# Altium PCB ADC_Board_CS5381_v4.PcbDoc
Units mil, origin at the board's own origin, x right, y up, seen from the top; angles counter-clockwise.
Board outline 7645 x 5670 mil, 2 copper layers (Top Layer, Bottom Layer); 112 components, 61 nets, 314 pads, 13 vias.
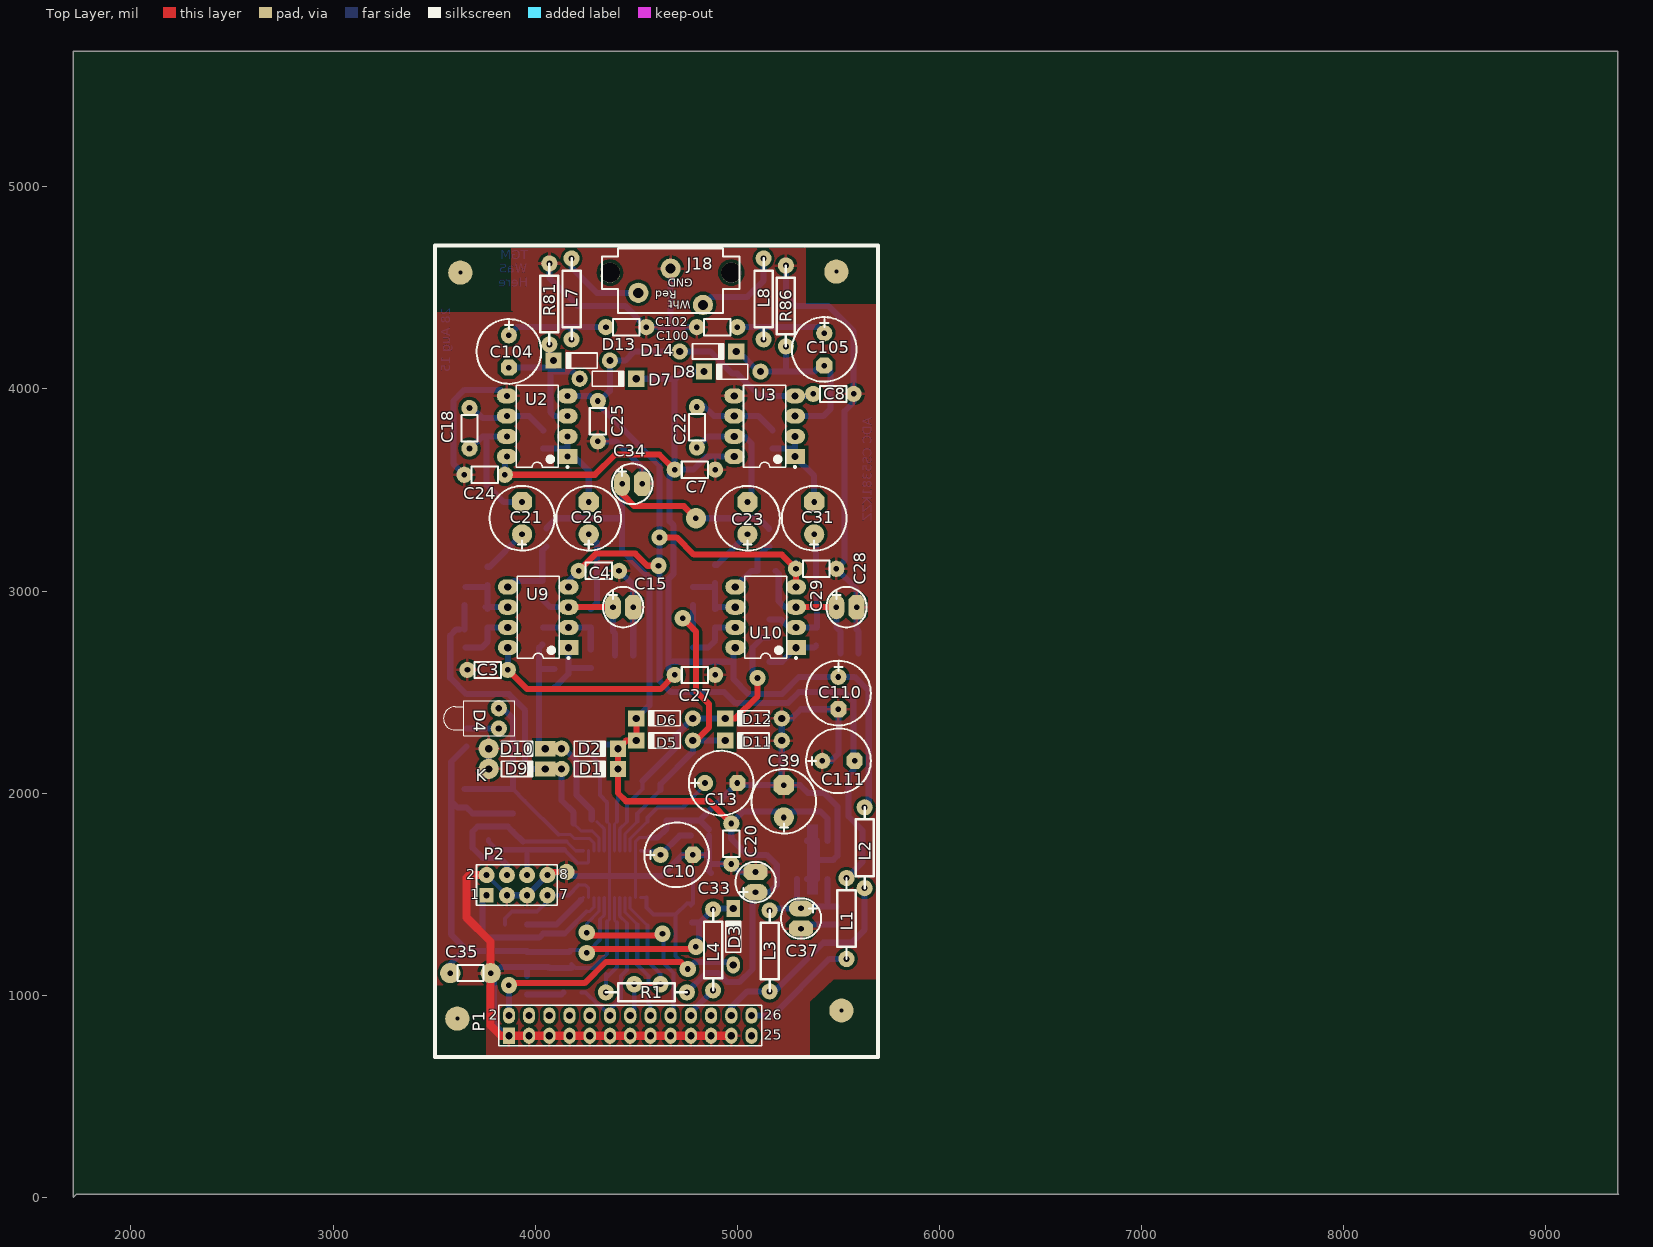
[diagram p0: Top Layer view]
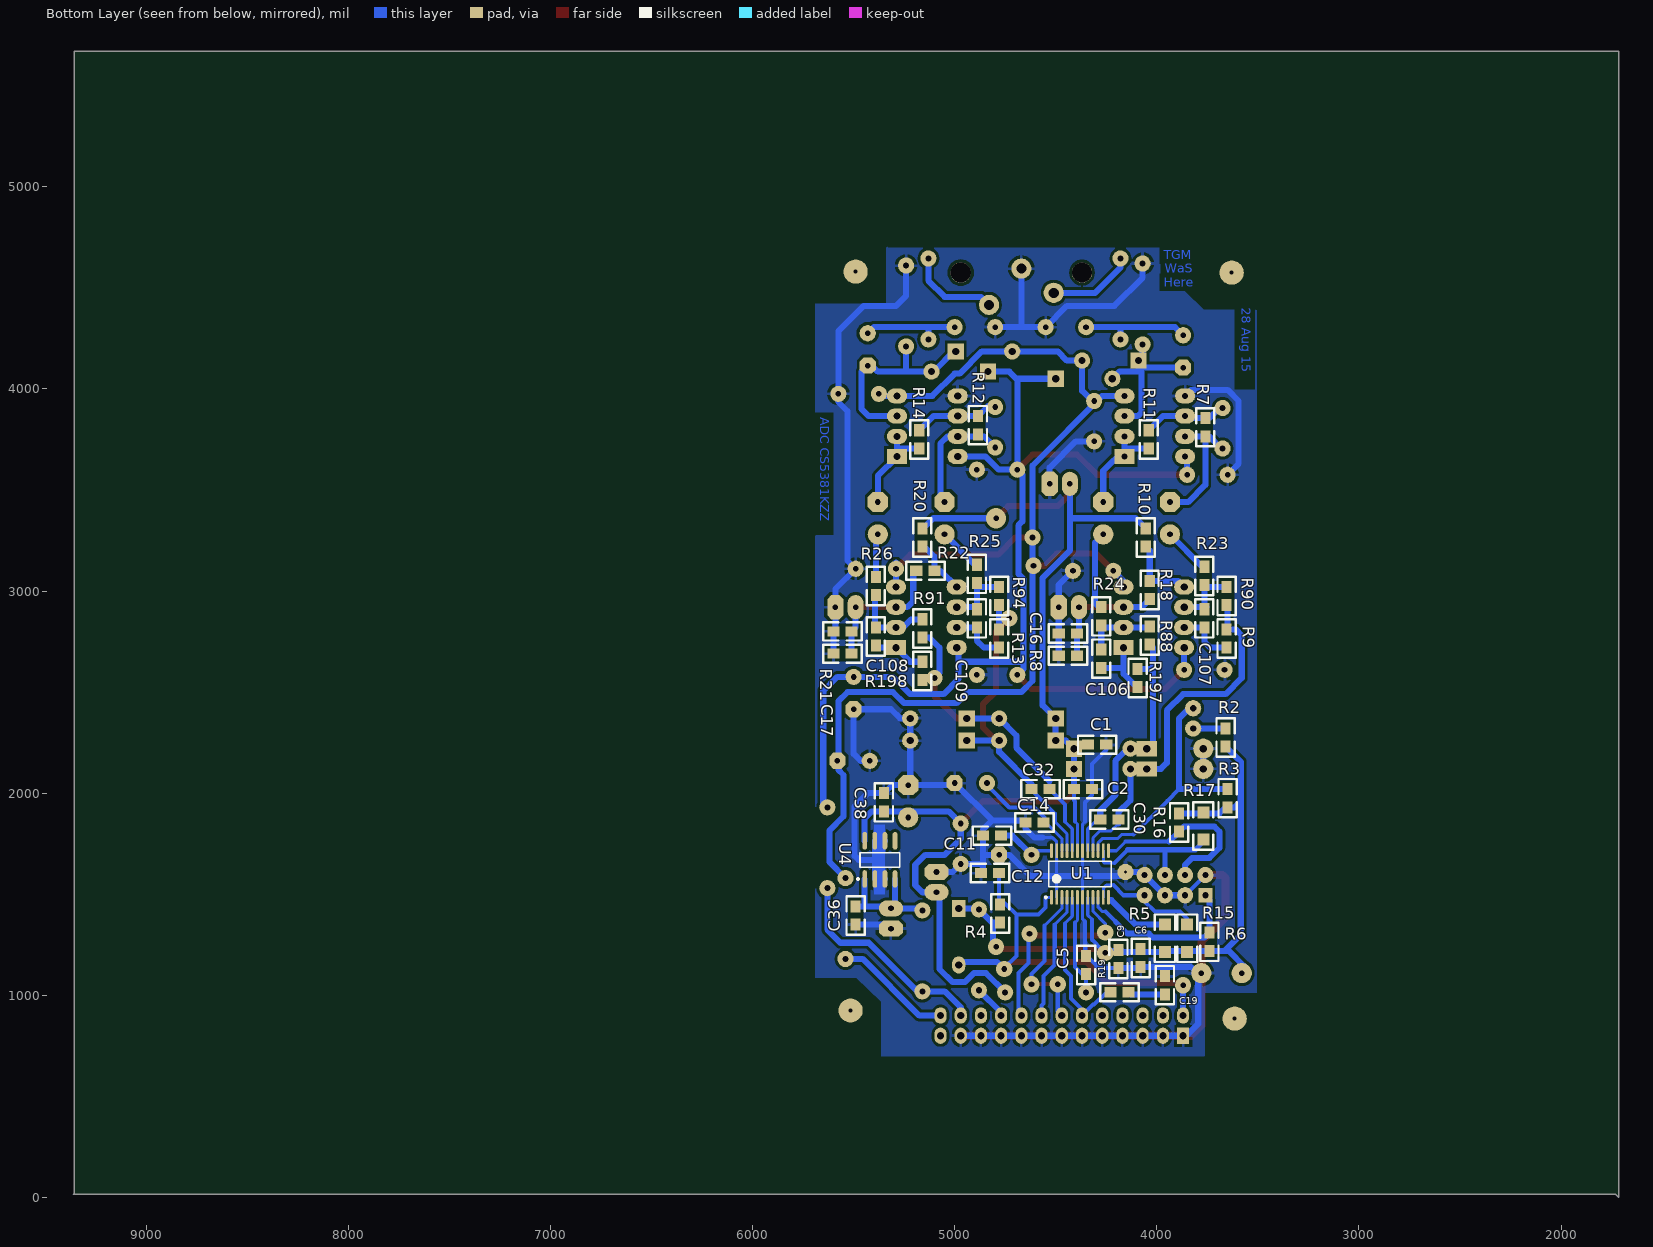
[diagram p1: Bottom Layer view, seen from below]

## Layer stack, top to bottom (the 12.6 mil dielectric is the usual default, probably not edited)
Top Layer: signal copper 1.4
Dielectric: core 12.6, FR-4, Dk 4.8
Bottom Layer: signal copper 1.4

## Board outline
1715,5670 9355,5670 9355,20 9360,15 1730,15 1715,0

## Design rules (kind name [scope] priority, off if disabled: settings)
Clearance Clearance_1 [(IsRegion)] p1: gap=15
Clearance [All] p2: gap=10
ComponentClearance [All] p1: gap=5 collisioncheckmode=3 verticalgap=10 showdistances=FALSE
HoleSize [All] p1: absolutevalues=TRUE maxlimit=125 minlimit=1 maxpercent=80.000 minpercent=20.000
PermittedLayers [All] p1: toplayerpermitted=TRUE bottomlayerpermitted=TRUE
PolygonConnect [All] p1: connectstyle=Relief reliefconductorwidth=15 reliefentries=4 polygonreliefangle="90 Angle"
RoutingVias [All] p1: holewidth=28 width=50 viastyle="Through Hole" minholewidth=28 minwidth=50 maxholewidth=28 maxwidth=50
SilkscreenOverComponentPads [All] p1: minsilkscreentomaskgap=10
SolderMaskExpansion [All] p1: expansion=4
Width [All] p1: maxlimit=255 minlimit=10 preferedwidth=10 minimp=50.000000 maximp=50.000000 favimp=50.000000
25 further rules are at their usual default settings.

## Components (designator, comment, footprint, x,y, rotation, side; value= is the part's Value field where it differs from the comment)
C1 "1uF" 0805 4340,2240 r180 bottom
C2 "10n" 0805 4410,2020 r180 bottom
C3 "100n" AXIAL0.2-pth#1 3865,2610 r180 top
C4 "100n" AXIAL0.2-pth#1 4415,3100 r180 top
C5 "10n" 0805 4350,1105 r90 bottom
C6 "1uF" 0805 4080,1230 r270 bottom
C7 "100n" AXIAL0.2-pth#1 4690,3600 r0 top
C8 "100n" AXIAL0.2-pth#1 5575,3975 r180 top
C9 "10n" 0805 4190,1225 r270 bottom
C10 "220uF" RB.16/.32-pth#1 4780,1695 r180 top
C11 "10n" 0805 4770,1790 r0 bottom
C12 "100n" 0805 4870,1605 r180 bottom
C13 "1uF" RB.16/.32-pth#1 5000,2050 r180 top
C14 "10n" 0805 4650,1855 r180 bottom
C15 "10uF" RB.1/.2 4485,2920 r180 top
C16 "100n" 0805 4395,2790 r0 bottom
C17 "100n" 0805 5510,2690 r0 bottom
C18 "33pF" AXIAL0.2-pth#1 3675,3905 r270 top
C19 "27pF" 0805 3960,1005 r90 bottom
C20 "100n" AXIAL0.2-pth#1 4970,1850 r270 top
C21 "47uF" RB.16/.32-pth#2 3935,3440 r270 top
C22 "33pF" AXIAL0.2-pth#1 4800,3910 r270 top
C23 "47uF" RB.16/.32-pth#2 5050,3440 r270 top
C24 "100n" AXIAL0.2-pth#1 3850,3575 r180 top
C25 "100n" AXIAL0.2-pth#1 4310,3740 r90 top
C26 "47uF" RB.16/.32-pth#2 4265,3440 r270 top
C27 "100n" AXIAL0.2-pth#1 4690,2585 r0 top
C28 "10uF" RB.1/.2 5590,2920 r180 top
C29 "100n" AXIAL0.2-pth#1 5490,3110 r180 top
C30 "2700pF" 0805 4280,1870 r180 bottom
C31 "47uF" RB.16/.32-pth#2 5380,3440 r270 top
C32 "2700pF" 0805 4530,2020 r0 bottom
C33 "10uF" RB.1/.2 5090,1610 r270 top
C34 "10uF" RB.1/.2 4530,3530 r180 top
C35 "100n" AXIAL0.2-pth#2 3580,1110 r0 top
C36 "100n" 0805 5490,1440 r270 bottom
C37 "220uF" RB.1/.2 5315,1330 r90 top
C38 "100n" 0805 5350,1910 r90 bottom
C39 "220uF" RB.16/.32-pth#2 5230,2040 r270 top
C100 "100pF" AXIAL0.2-pth#1 4350,4305 r0 top
C102 "100pF" AXIAL0.2-pth#1 4800,4305 r0 top
C104 "47uF" RB.16/.32-PTH 3870,4105 r90 top
C105 "47uF" RB.16/.32-PTH 5430,4115 r90 top
C106 "1nF" 0805 4275,2620 r90 bottom
C107 "1nF" 0805 3765,2910 r270 bottom
C108 "1nF" 0805 5390,2730 r90 bottom
C109 "1nF" 0805 4890,2910 r270 bottom
C110 "22uF" RB.16/.32-pth#1 5500,2415 r90 top
C111 "22uF" RB.16/.32-pth#1 5580,2160 r180 top
D1 "BAT85" DIO7.1-3.9x1.9#1 4270,2120 r0 top
D2 "BAT85" DIO7.1-3.9x1.9#1 4270,2220 r0 top
D3 "Diode 1N914" DIO7.1-3.9x1.9#2 4980,1290 r90 top
D4 "LED0" LED-1 3820,2370 r180 top
D5 "BAT85" DIO7.1-3.9x1.9#1 4640,2260 r180 top
D6 "BAT85" DIO7.1-3.9x1.9#1 4640,2370 r180 top
D7 "BAT85" DIO7.1-3.9x1.9#1 4360,4050 r0 top
D8 "BAT85" DIO7.1-3.9x1.9#1 4975,4085 r180 top
D9 "BAT85" DIO7.1-3.9x1.9#3 3910,2120 r0 top
D10 "BAT85" DIO7.1-3.9x1.9#3 3910,2220 r0 top
D11 "BAT85" DIO7.1-3.9x1.9#1 5080,2260 r180 top
D12 "BAT85" DIO7.1-3.9x1.9#1 5080,2370 r180 top
D13 "BAT85" DIO7.1-3.9x1.9#1 4230,4140 r180 top
D14 "BAT85" DIO7.1-3.9x1.9#1 4855,4185 r0 top
J18 "Analog Input" RCA-PCB-2IP 4510,4475 r180 top
L1 "bead" AXIAL0.4-PTH 5540,1580 r270 top
L2 "bead" AXIAL0.4-PTH 5630,1930 r270 top
L3 "bead" AXIAL0.4-PTH 5160,1020 r90 top
L4 "bead" AXIAL0.4-PTH 4880,1425 r270 top
L7 "bead" AXIAL0.4-PTH 4180,4645 r270 top
L8 "bead" AXIAL0.4-PTH 5130,4245 r90 top
P1 "Header 13X2" HDR2X13 3870,800 r0 top
P2 "Header 4X2" HDR2X4 3760,1495 r0 top
R1 "5R1" AXIAL0.4-PTH 4750,1015 r180 top
R2 "1K" 0805 3660,2320 r270 bottom
R3 "10K" 0805 3650,2020 r270 bottom
R4 "10K" 0805 4774.8,1449.8 r270 bottom
R5 "10K" 1206 3960,1350 r270 bottom
R6 "10K" 0805 3740,1310 r270 bottom
R7 "4k7" 0805 3760,3855 r270 bottom
R8 "10K" 0805 4395,2680 r0 bottom
R9 "91" 0805 3655,2720 r90 bottom
R10 "10K" 0805 4055,3310 r270 bottom
R11 "4k7" 0805 4040,3705 r90 bottom
R12 "4k7" 0805 4885,3865 r270 bottom
R13 "91" 0805 4780,2720 r90 bottom
R14 "4k7" 0805 5175,3705 r90 bottom
R15 "10K" 1206 3850,1350 r270 bottom
R16 "10K" 0805 3890,1810 r90 bottom
R17 "10K" 1206 3770,1770 r90 bottom
R18 "8r2" 0805 4035,3050 r270 bottom
R19 "100R" 0805 4230,1015 r180 bottom
R20 "10K" 0805 5160,3310 r270 bottom
R21 "10K" 0805 5510,2800 r0 bottom
R22 "8r2" 0805 5100,3100 r0 bottom
R23 "680" 0805 3765,3120 r270 bottom
R24 "680" 0805 4275,2920 r270 bottom
R25 "680" 0805 4890,3130 r270 bottom
R26 "680" 0805 5390,3070 r270 bottom
R81 "100K" AXIAL0.4-PTH 4070,4620 r270 top
R86 "100K" AXIAL0.4-PTH 5240,4610 r270 top
R88 "680" 0805 4035,2825 r270 bottom
R90 "680" 0805 3655,3020 r270 bottom
R91 "680" 0805 5160,2860 r270 bottom
R94 "680" 0805 4780,3020 r270 bottom
R197 "91" 0805 4095,2525 r90 bottom
R198 "91" 0805 5160,2650 r270 bottom
U1 "CS5361" TSOP65P640X120-24M 4380,1600 r90 bottom
U2 "NE5532" DIP-8#1 4010,3815 r180 top
U3 "NE5532" DIP-8#2 5135,3815 r180 top
U4 "MC33375D-5.0R2" 751-05_N 5370,1670 r90 bottom
U9 "NE5532" DIP-8#3 4015,2870 r180 top
U10 "NE5532" DIP-8#3 5140,2870 r180 top

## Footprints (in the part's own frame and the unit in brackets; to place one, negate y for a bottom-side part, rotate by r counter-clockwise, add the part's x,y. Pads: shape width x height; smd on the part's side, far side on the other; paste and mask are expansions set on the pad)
751-05_N [mm] "SOIC, 8-Leads, Body 4.9x3.9mm, Pitch 1.27mm, IPC Medium Density"
  oval 2.2x0.6 smd: 1(-2.4,1.905) 2(-2.4,0.635) 3(-2.4,-0.635) 4(-2.4,-1.905) 5(2.4,-1.905) 6(2.4,-0.635) 7(2.4,0.635) 8(2.4,1.905)
  silkscreen extent -2.52,-2.5 0.9,2.88, body extent -1.95,-2.45 1.95,2.45, height 1.75
0805 [mil]
  rect 60x50 smd: 1(0,0) 2(90,0)
  silkscreen extent -50,-45 140,45
1206 [mil]
  rect 60x60 smd: 1(0,0) 2(135,0)
  silkscreen extent -50,-50 185,50, body extent -56,-56 191,56, height 8
AXIAL0.2-pth#1 [mil]
  round 80 hole 28: 1(0,0) 2(200,0)
  silkscreen extent 35,-40 165,40
AXIAL0.2-pth#2 [mil]
  round 100 hole 28: 1(0,0) 2(200,0)
  silkscreen extent 35,-40 165,40, body extent 30,-45 170,45, height 200
AXIAL0.4-PTH [mil]
  round 80 hole 30: 1(0,0) 2(400,0)
  silkscreen extent 0,-45 400,45, body extent 60,-45 340,45
DIO7.1-3.9x1.9#1 [mil] "Diode, Axial; Body 3.8 x 1.9 mm (LxDia. max), Lead Dia. 0.53 mm (max)"
  round 80 hole 35.43: 1(-139.76,0)
  rect 80x80 hole 35.43: 2(139.76,0)
  silkscreen extent -77,-37 81,37
DIO7.1-3.9x1.9#2 [mil] "Diode, Axial; Body 3.8 x 1.9 mm (LxDia. max), Lead Dia. 0.53 mm (max)"
  oval 85x65 hole 35.43: 1(-139.76,0)
  rect 85x65 hole 35.43: 2(139.76,0)
  silkscreen extent -77,-37 81,37
DIO7.1-3.9x1.9#3 [mil] "Diode, Axial; Body 3.8 x 1.9 mm (LxDia. max), Lead Dia. 0.53 mm (max)"
  round 100 hole 35.43: 1(-139.76,0)
  rect 100x75 hole 35.43: 2(139.76,0)
  silkscreen extent -77,-37 81,37
DIP-8#1 [mil] "DIP; 8 Leads; Row Spacing 7.62 mm; Pitch 2.54 mm"
  rect 100x75 hole 30: 1(-150,150)
  oval 100x75 hole 30: 2(-150,50) 3(-150,-50) 4(-150,-150) 5(150,-150) 6(150,-50) 7(150,50) 8(150,150)
  silkscreen extent -155,-203 104,206, body extent -142,-203 142,203, height 200
DIP-8#2 [mil] "DIP; 8 Leads; Row Spacing 7.62 mm; Pitch 2.54 mm"
  rect 100x75 hole 35.43: 1(-150,150)
  oval 100x75 hole 35.43: 2(-150,50) 3(-150,-50) 4(-150,-150) 5(150,-150) 6(150,-50) 7(150,50) 8(150,150)
  silkscreen extent -155,-203 104,206, body extent -142,-203 142,203, height 200
DIP-8#3 [mil] "DIP, 8-Pin, Row Spacing 7.62 mm, Pitch 2.54 mm"
  rect 100x75 hole 36: 1(-150,150)
  oval 100x75 hole 36: 2(-150,50) 3(-150,-50) 4(-150,-150) 5(150,-150) 6(150,-50) 7(150,50) 8(150,150)
  silkscreen extent -155,-203 104,206, body extent -142,-203 142,203, height 210
HDR2X4 [mil] "Connector; Header; 4x2 Position"
  rect 70x70 hole 30: 1(0,0)
  round 80 hole 30: 2(0,100) 3(100,0) 4(100,100) 5(200,0) 6(200,100) 7(300,0) 8(300,100)
  silkscreen extent -50,-50 350,150
HDR2X13 [mil] "Connector; Header; 13x2 Position"
  rect 60x80 hole 35.43: 1(0,0)
  oval 60x80 hole 35.43: 2(0,100) 3(100,0) 4(100,100) 5(200,0) 6(200,100) 7(300,0) 8(300,100) 9(400,0) 10(400,100) 11(500,0) 12(500,100) 13(600,0) 14(600,100) 15(700,0) 16(700,100) 17(800,0) 18(800,100) 19(900,0) 20(900,100) 21(1000,0) 22(1000,100) 23(1100,0) 24(1100,100) 25(1200,0) 26(1200,100)
  silkscreen extent -50,-50 1250,150
LED-1 [mil] "Typical RED GaAs LED; 2 Leads"
  round 80 hole 31.5: 1(0,50) 2(0,-50)
  silkscreen extent -79,-87 274,87
RB.1/.2 [mil]
  oval 80x120 hole 28: 1(100,0)
  oct 80x120 hole 28: 2(0,0)
  silkscreen extent -50,-100 150,100, body extent -50,-100 150,100
RB.16/.32-pth#1 [mil]
  round 80 hole 28: 1(160,0)
  oct 80x80 hole 28: 2(0,0)
  silkscreen extent -80,-160 240,160
RB.16/.32-pth#2 [mil]
  round 100 hole 28: 1(160,0)
  oct 100x100 hole 28: 2(0,0)
  silkscreen extent -80,-160 240,160, body extent -80,-160 240,160, height 540
RB.16/.32-PTH [mil]
  round 80 hole 28: 1(160,0)
  oct 80x80 hole 28: 2(0,0)
  silkscreen extent -80,-160 240,160, body extent -80,-160 240,160, height 540
RCA-PCB-2IP [mil]
  round 100 hole 100: 0(-460,-100) 0(140,-100)
  round 100 hole 50: 1(0,0) 2(-160,-120) 3(-320,60)
  silkscreen extent -500,-220 180,100
TSOP65P640X120-24M [mm] "TSOP, 24-Leads, Body 7.9x4.5mm (max), Pitch 0.65mm, IPC Low Density"
  oval 1.85x0.35 smd: 1(-2.925,3.575) 2(-2.925,2.925) 3(-2.925,2.275) 4(-2.925,1.625) 5(-2.925,0.975) 6(-2.925,0.325) 7(-2.925,-0.325) 8(-2.925,-0.975) 9(-2.925,-1.625) 10(-2.925,-2.275) 11(-2.925,-2.925) 12(-2.925,-3.575) 13(2.925,-3.575) 14(2.925,-2.925) 15(2.925,-2.275) 16(2.925,-1.625) 17(2.925,-0.975) 18(2.925,-0.325) 19(2.925,0.325) 20(2.925,0.975) 21(2.925,1.625) 22(2.925,2.275) 23(2.925,2.925) 24(2.925,3.575)
  silkscreen extent -3.05,-3.95 1.6,4.43, body extent -2.25,-3.95 2.25,3.95, height 1.2

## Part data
C1 C3 C4 C5 C6 C7 C8 C9 C11 C14 C16 C17 C18 C20 C22 C24 C25 C27 C29 C30 C32 C35 C36 C38 C100 C102 C104 C105 C106 C107 C108 C109: library part CAP
C2: library part Cap
C10 C13 C15 C21 C23 C26 C28 C31 C33 C34 C37 C39 C110 C111: library part CAPACITOR, "Capacitor"
C12: library part Cap, "Capacitor"
C19: library part CAP, "Capacitor"
D1 D2 D5 D6 D7 D8 D9 D10 D11 D12 D13 D14: library part "Diode 1N914", "Shottky Diode"
D3: "High Conductance Fast Diode"
D4: "Typical INFRARED GaAs LED"
J18: library part RCA-PCB-2IP
L1 L2 L3 L4 L7 L8: library part INDUCTOR1
P1: "Header, 13-Pin, Dual row"
P2: "Header, 4-Pin, Dual row"
R1 R2 R3 R4 R5 R6 R7 R8 R9 R10 R11 R12 R13 R14 R15 R16 R17 R18 R19 R20 R21 R22 R23 R24 R25 R26 R81 R86 R88 R90 R91 R94 R197 R198: library part RES2
U2 U3 U9 U10: library part LF353N(8), "Fast Settling Dual Operational Amplifier"
U4: "Low Dropout 300mA Voltage Regulator with ON/OFF Control"

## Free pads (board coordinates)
  round 120 hole 20: 0(3615,885) 0(3630,4575) 0(5490,4580) 0(5515,925)
  round 80 hole 15: 1(4155,1610)

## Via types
v1: diameter 80, hole 28, Top Layer to Bottom Layer, 12 vias
v2: diameter 100, hole 28, Top Layer to Bottom Layer, 1 vias

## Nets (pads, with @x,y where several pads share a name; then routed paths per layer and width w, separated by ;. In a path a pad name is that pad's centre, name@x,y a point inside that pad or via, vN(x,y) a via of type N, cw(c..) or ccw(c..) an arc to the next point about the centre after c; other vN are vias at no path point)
+9V: C3.1 C7.1 C24.1 C27.1 C110.1 D7.2 D8.2 L2.1 U2.8 U3.8 U9.8 U10.8 | length 6086.5
  Top Layer w30: C24.1 4295,3575 4395,3675 4615,3675 C7.1 ; C3.1 3960,2515 4620,2515 C27.1
  Bottom Layer w30: C24.1 3850,3655 U2.8 ; C3.1@3865,2605 C3.1 U9.8 ; D7.2 4695,4050 ; C27.1 4660,2615 4660,2650 ; D8.2 4730,4085 4695,4050 ; U3.8 4846.92,3665 4781.92,3600 C7.1@4695,3600 ; U10.8 4980,2710 4980,2650 ; L2.1 5650,1950 5650,2505.36 5580.36,2575 C110.1 5305,2575 5220,2490 5055,2490 4980,2565 4980,2650 ; 4660,2650 4980,2650 ; 4660,2650 4660,3060 4685,3085 4685,3325 4665,3345 4665,3575 C7.1 ; C7.1@4690,3590 4700,3590 4690,3580 C7.1@4690,3590 ; C7.1@4690,3590 4685,3590 C7.1@4690,3595 ; C7.1@4690,3590 C7.1@4690,3595 ; C7.1@4690,3595 C7.1@4695,3600 ; C7.1@4690,3595 C7.1 ; C7.1 C7.1@4695,3600 ; C7.1 4690,4045 4695,4050
+9V_I: L2.2 L3.1 P1.24 | length 1084.5
  Bottom Layer w30: P1.24@4970,920 P1.24 4970,940 5050,1020 L3.1 5185,1020 5425,1260 5565,1260 5630,1325 L2.2
-9V: C4.2 C8.2 C25.2 C29.2 C111.2 D13.1 D14.1 L1.1 U2.4 U3.4 U9.4 U10.4 | length 6554.5
  Top Layer w30: C4.2 4300,3185 4495,3185 4555,3125 v1(4610,3125) ; v1(4615,3265) 4615,3285 4635,3265 4700,3265 4785,3180 5220,3180 C29.2 U10.4
  Bottom Layer w30: U2.4@4160,3975 U2.4 4270,3965 4615,3620 v1(4615,3265) 4615,2555 4670,2500 4935,2500 4990,2445 5250,2445 5305,2500 5530,2500 5575,2455 5575,2115 5550,2090 5550,1885 5620,1815 5620,1660 L1.1 ; U9.4 4165,3050 C4.2 ; C25.2@4310,3930 4369.76,3989.76 D13.1 4445,4140 4490,4185 D14.1 4865,4185 4975,4075 5000,4075 5110,3965 U3.4 5365,3965 C8.2 ; U10.4 C29.2 C29.2@5290,3140
CCLK: P1.8
CDIN: P1.10
CDOUT: P1.6
CS_L: P1.4
GND: C1.2 C2.2 C3.2 C4.1 C5.2 C6.2 C7.2 C8.1 C9.2 C10.2 C11.2 C12.1 C13.2 C14.1 C15.2 C16.2 C17.2 C19.2 C20.2 C24.2 C25.1 C27.2 C28.2 C29.1 C33.2 C34.2 C35.2 C36.2 C37.2 C38.2 C39.2 C100.2 C102.1 C110.2 C111.1 D9.1 D10.1 D11.1 D12.1 J18.2 P1.1 P1.3 P1.5 P1.7 P1.9 P1.11 P1.13 P1.15 P1.17 P1.19 P1.21 P1.23 P2.2 P2.3 P2.5 P2.8 pad.1 R8.2 R21.2 R81.1 R86.1 U1.2 U1.7 U1.18 U1.23 U2.5 U3.5 U4.2 U4.3 U4.6 U4.7 | length 15469.3
  Top Layer w30: P2.8 4075,1610 pad.1
  Top Layer w40: P2.2 3675,1595 3660,1580 3660,1385 3780,1265 C35.2 3780,850 3830,800 P1.1 P1.3 P1.5 P1.7 P1.9 P1.11 P1.13 P1.15 P1.17 P1.19 P1.21 P1.23
  Bottom Layer w15: 4355,1363.93 4367.2,1376.14 U1.7 4367.2,1585 ; 4355,1860 4367.2,1847.8 U1.18 4367.2,1590 ; U1.2 4495.16,1585 ; 4495.16,1590 U1.23 4495.16,1759.8 4515.36,1780 4565,1780
  Bottom Layer w20: P2.2 P2.3 ; 4110,1610 pad.1 4180,1610 pad.1@4187.5,1602.5 ; C9.2@4180,1155 4200,1135 4285,1135 4355,1205 4355,1363.93 ; C1.2 4250,2215 4320,2145 C2.2 ; C2.2@4320,2025 C2.2 ; 4355,1860 4355,1955 4320,1990 C2.2
  Bottom Layer w30: C24.2@3650,3570 C24.2 3595,3630 3595,3940 3650,3995 3830,3995 U2.5 ; C35.2@3770,1090 3790,1090 C35.2@3795,1085 ; D10.1 D9.1 D9.1@3780,2120 ; P2.3 P2.5 P2.8 4075,1610 pad.1 pad.1@4160,1610 ; C19.2 3960,1140 ; R81.1 4070,4550 4210,4410 4445,4410 C100.2 C102.1 ; pad.1@4175,1590 4367.2,1590 4495.16,1590 4625,1590 4730,1695 C10.2 4855,1695 ; C9.2@4180,1135 4070,1135 4065,1140 3830,1140 3795,1105 C35.2@3795,1085 ; C25.1 4400,3740 4530,3610 C34.2 ; C4.1 4485,3030 C15.2 C16.2 R8.2 ; 4565,1780 4605,1780 4650,1825 4650,1865 4815,1865 ; 4670,4310 J18.2 ; C11.2 4860,1650 ; 4860,1820 4815,1865 ; C12.1 4860,1615 4860,1650 ; P1.23 P1.1 3855,800 3795,860 C35.2@3795,1085 ; C33.2 5010,1610 C20.2 4860,1650 ; R86.1 5240,4460 5290,4410 5450,4410 5575,4285 C8.1 5575,3935 5530,3890 5530,3150 C29.1 5590,3010 5590,2810 R21.2 C17.2 ; C37.2 5335,1350 C36.2 ; U4.3 U4.2 5395,1670 ; U4.6 U4.7 5395,1670 ; C111.1 5465,2160 5500,2195 C110.2 5315,2415 5270,2370 D12.1 D11.1 5219.76,2050.24 C39.2 ; 4815,1865 C13.2 5010,2040 C39.2 ; C39.2 5310,2040 C38.2 5430,2000 5495,1935 5495,1690 5475,1670 5395,1670
HPF_L: P2.7 R15.1 U1.11 | length 589.3
  Bottom Layer w15: 4215,1545 4250,1545 4264.84,1530.16 U1.11
  Bottom Layer w20: R15.1 3850,1380 3885,1415 4010,1415 4060,1465 P2.7 4165,1495 4215,1545
  Bottom Layer w25: P2.7 P2.7@4065,1490
LRCK: P1.14 U1.3 | length 812.5
  Top Layer w20: v1(4490,1055) v1(4620,1055)
  Bottom Layer w15: U1.3 4469.57,1430.43 4555,1345
  Bottom Layer w20: P1.14@4470,920 P1.14 4490,920 v1(4490,1055) ; 4555,1345 4555,1275 4555,1170 4620,1105 v1@4620,1080 ; v1(4620,1055) v1@4620,1080 ; v1@4625,1085 v1@4620,1080
M0: P2.4 R16.1 U1.13 | length 944.5
  Bottom Layer w15: 4155,1760 4199.84,1715.16 U1.13
  Bottom Layer w20: 3940,1760 4155,1760
  Bottom Layer w30: P2.4 3860,1645 3825,1680 3740,1680 3690,1730 3690,1810 3715,1835 3865,1835 R16.1 3940,1760
M1: P2.6 R17.1 U1.14 | length 745.7
  Bottom Layer w15: 4210,1655 4260,1655 4264.84,1659.84 U1.14
  Bottom Layer w20: 4145,1720 4180,1685 4210,1655
  Bottom Layer w25: R17.1 3770,1760 3810,1720 3960,1720 ; P2.6 3960,1720 ; 4145,1720 3960,1720
  Bottom Layer w30: P2.6 P2.6@3960,1610
MCLK: P1.12 R19.1 U1.5 | length 822.9
  Bottom Layer w15: U1.5 4418.39,1391.61 4455,1355
  Bottom Layer w20: R19.1 4250,1015 4310,955 4315,955 P1.12 4370,930 4425,985 4425,1095 4455,1125 4455,1275 4455,1355
MDIV: P2.1 R6.1 U1.10 | length 865.8
  Bottom Layer w15: 4255,1415 4270,1415 4290.43,1435.43 U1.10
  Bottom Layer w20: 4205,1365 4255,1415
  Bottom Layer w25: 4145,1305 4205,1365
  Bottom Layer w30: P2.1 3740,1475 R6.1 3765,1285 4020,1285 4040,1305 4145,1305
NetC5_1: C5.1 R1.2 U1.6 | length 517.7
  Bottom Layer w15: U1.6 4392.8,1371.85 4405,1359.64
  Bottom Layer w20: R1.2 C5.1@4350,1085 ; C5.1 C5.1@4350,1085 ; 4405,1359.64 4405,1275 4405,1140 C5.1@4350,1085
NetC10_1: C10.1 C11.1 U1.24 | length 312
  Bottom Layer w15: U1.24 4599.84,1715.16 C10.1
  Bottom Layer w30: C10.1@4620,1710 C10.1 4715,1790 C11.1
NetC18_1: C18.1 R7.1 R11.2 U2.6 | length 418.8
  Bottom Layer w30: C18.1 3690,3905 3740,3855 3850,3855 U2.6 3970,3865 R11.2
NetC18_2: C18.2 C21.2 R7.2 U2.7 | length 700.1
  Bottom Layer w30: C18.2@3670,3705 3680,3705 3740,3765 R7.2 ; U2.7@3895,3765 U2.7 R7.2 ; C21.2 3845,3440 3760,3525 R7.2
NetC19_1: C19.1 R19.2 | length 184.1
  Bottom Layer w30: C19.1 4130,1005 R19.2
NetC21_1: C21.1 R23.1 | length 236.3
  Bottom Layer w30: R23.1 3775,3120 C21.1
NetC22_1: C22.1 R12.1 R14.2 U3.6 | length 419.7
  Bottom Layer w30: C22.1@4805,3915 4835,3915 R12.1 U3.6 5105,3865 R14.2
NetC22_2: C22.2 C23.2 R12.2 U3.7 | length 598.5
  Bottom Layer w30: C22.2@4805,3715 4855,3765 U3.7 5035,3765 5070,3730 5070,3460 C23.2
NetC23_1: C23.1 R25.1 | length 222.1
  Bottom Layer w30: R25.1 4900,3130 C23.1
NetC26_1: C26.1 R24.1 | length 413.1
  Bottom Layer w30: C26.1@4255,3270 C26.1 4305,3240 4305,2940 R24.1@4275,2910
NetC26_2: C26.2 R11.1 U2.1 U2.2 | length 525.6
  Bottom Layer w30: R11.1 4155,3705 4265,3595 C26.2 ; U2.1 U2.2
NetC30_1: C30.1 D2.1 D10.2 R88.2 R197.2 U1.17 | length 1275.6
  Bottom Layer w15: C30.1@4305,1860 4341.61,1823.39 U1.17
  Bottom Layer w30: 4020,2615 R197.2 ; R88.2 4020,2720 4020,2239.76 D10.2@4049.76,2210 ; D10.2 D2.1 ; D2.1@4130.24,2210 4155,2210 4205,2160 4205,1990 4280,1915 C30.1
NetC30_2: C30.2 D1.1 D9.2 R9.2 R90.2 U1.16 | length 1840.4
  Top Layer w20: D1.1@4120,2120 D1.1
  Bottom Layer w15: C30.2@4190,1850 4227.5,1812.5 4282.5,1812.5 4316.02,1778.98 U1.16
  Bottom Layer w20: D9.2 D1.1
  Bottom Layer w30: 3625,2810 3610,2810 3580,2780 3580,2570 3660,2490 3870,2490 3950,2410 3950,2150 3980,2120 D9.2 D9.2@4010,2120 ; R9.2@3650,2810 R90.2@3650,2930 ; D1.1 4130.24,1964.76 4190,1905 C30.2@4190,1850
NetC31_1: C31.1 R26.1 | length 238.3
  Bottom Layer w30: C31.1@5365,3275 5370,3280 C31.1 ; C31.1@5375,3275 C31.1 ; R26.1 5390,3270 C31.1
NetC31_2: C31.2 R14.1 U3.1 U3.2 | length 514.4
  Bottom Layer w30: R14.1 5285,3705 U3.1 ; U3.2 U3.1 ; C31.2 5380,3570 U3.1
NetC32_1: C32.1 D6.1 D12.2 R91.2 R198.2 U1.20 | length 1526.4
  Top Layer w30: D12.2 4990,2370 5100,2480 v1(5100,2570)
  Bottom Layer w15: U1.20 4418.39,1823.39 4455,1860
  Bottom Layer w20: 4455,1860 4455,1945 C32.1 4530,2060
  Bottom Layer w30: 4530,2060 4695,2225 4695,2285.24 D6.1 D12.2 ; v1(5100,2570) 5075,2595 5075,2720 5125,2770 R91.2
NetC32_2: C32.2 D5.1 D11.2 R13.2 R94.2 U1.21 | length 1747.5
  Top Layer w30: v1(4730,2865) 4795,2800 4795,2505 4860,2440 4860,2325 4795,2260 D5.1
  Bottom Layer w15: U1.21 4443.98,1798.98 4505,1860
  Bottom Layer w20: 4505,1860 4505,1900 C32.2@4620,2015
  Bottom Layer w30: C32.2@4620,2015 4620,2045 4779.76,2204.76 D5.1 D11.2 ; v1(4730,2865) 4720,2865 4715,2870 4780,2870 ; R13.2 4780,2870 ; R94.2 4780,2870
NetC36_1: C36.1 C37.1 L3.2 U4.1 U4.4 | length 627.6
  Bottom Layer w30: L3.2 5170,1430 C37.1 ; U4.4 5295,1450 C37.1 ; U4.1 5445,1440 ; C36.1 5445,1440 ; C37.1 5325,1440 5445,1440
NetC100_1: C100.1 C104.1 L7.2 | length 556.6
  Bottom Layer w30: C104.1 3910,4305 4180,4305 ; L7.2 4180,4305 ; C100.1 4180,4305
NetC102_2: C102.2 C105.1 L8.1 | length 497.4
  Bottom Layer w30: C102.2 5240,4305 5400,4305 C105.1 ; L8.1 5130,4300
NetC104_2: C104.2 D7.1 D13.2 R81.2 U2.3 | length 754.3
  Bottom Layer w30: C104.2 D13.2@4055,4105 ; R81.2 4070,4160.24 D13.2 D13.2@4075,4124.76 ; 4090.24,4085 4185.24,4085 D7.1 ; D13.2@4090.24,4100.24 4075,4085 4075,3885 4095,3865 U2.3
NetC105_2: C105.2 D8.1 D14.2 R86.2 U3.3 | length 1035.1
  Bottom Layer w30: D14.2@4994.76,4195 5104.76,4085 D8.1 5240,4085 ; R86.2 5240,4085 ; U3.3 5425,3865 5460,3900 5460,4085 C105.2 5410,4115 5380,4085 5240,4085
NetC106_1: C106.1 R197.1 U9.1 | length 331.9
  Bottom Layer w30: R197.1 4100,2525 4165,2590 U9.1 ; 4170,2620 C106.1
NetC106_2: C106.2 R24.2 R88.1 U9.2 | length 345
  Bottom Layer w30: R88.1@4040,2820 U9.2 4275,2820 C106.2
NetC107_1: C107.1 R23.2 R90.1 U9.6 | length 330
  Bottom Layer w30: R90.1 R23.2@3755,3020 ; C107.1@3755,2920 C107.1@3765,2920 ; C107.1 C107.1@3765,2920 ; R23.2 C107.1@3765,2920 ; U9.6 C107.1@3765,2920
NetC107_2: C107.2 R9.1 U9.7 | length 282.4
  Bottom Layer w30: R9.1 3735,2720 3765,2750 C107.2 ; C107.2@3775,2820 U9.7
NetC108_1: C108.1 R198.1 U10.1 | length 263.1
  Bottom Layer w30: R198.1 5220,2650 U10.1 5380,2720 C108.1
NetC108_2: C108.2 R26.2 R91.1 U10.2 | length 411.6
  Bottom Layer w30: R91.1 5215,2860 5255,2820 U10.2 C108.2 5395,2820 R26.2@5395,2980
NetC109_1: C109.1 R25.2 R94.1 U10.6 | length 354.1
  Bottom Layer w30: R94.1 R25.2@4870,3020 ; R25.2 C109.1 4900,2920 U10.6 U10.6@5020,2920
NetC109_2: C109.2 R13.1 U10.7 | length 339.5
  Bottom Layer w30: R13.1 4855,2720 4890,2755 C109.2 U10.7 U10.7@4940,2820
NetD4_1: D4.1 R2.1 | length 160
  Bottom Layer w30: R2.1 D4.1
NetJ18_1: J18.1 L7.1 | length 426.8
  Bottom Layer w30: L7.1 4180,4600 4305,4475 J18.1
NetJ18_3: J18.3 L8.2 | length 459.7
  Bottom Layer w30: J18.3 4870,4455 5050,4455 5130,4535 L8.2
NetL1_2: L1.2 P1.26 | length 586
  Bottom Layer w30: P1.26 5175,900 5455,1180 L1.2
NetL4_2: L4.2 P1.20 | length 200.6
  Bottom Layer w30: P1.20@4770,920 P1.20 4770,915 L4.2 ; L4.2@4860,1010 L4.2@4870,1010
NetR5_1: R5.1 U1.12 | length 335.1
  Bottom Layer w15: 4225.43,1471.02 U1.12
  Bottom Layer w30: R5.1 4104.41,1350 4225.43,1471.02
OVFL_L: D4.2 R3.1 U1.15 | length 1230.5
  Bottom Layer w15: 4115,1795 4175,1795 4195,1775 4270,1775 4290.43,1754.57 U1.15
  Bottom Layer w20: 3890,2020 3950,1960 4115,1795
  Bottom Layer w30: R3.1 3890,2020 3890,2370 3840,2420 D4.2
RST_L: C12.2 D3.1 P1.2 R4.1 U1.1 | length 2160.9
  Top Layer w30: v1(3870,1050) 3880,1060 4245,1060 4350,1165 4720,1165 v1(4755,1130)
  Bottom Layer w15: U1.1 4550.16,1484.84
  Bottom Layer w20: 4550.16,1484.84 4550.16,1434.84 4585,1400 4695,1400 ; v1@4757.5,1132.5 4695,1195 4695,1400 ; R4.1@4770,1445 R4.1 R4.1@4780,1455 ; C12.2 4780,1515 R4.1@4780,1455 ; 4695,1400 4750,1455 R4.1@4780,1455
  Bottom Layer w30: v1@3860,1060 v1(3870,1050) P1.2 ; v1(4755,1130) 4757.5,1132.5 4790,1165 4965.24,1165 D3.1
SCLK: P1.16 U1.4 | length 637
  Bottom Layer w15: U1.4 4443.98,1411.02 4505,1350
  Bottom Layer w20: 4505,1350 4505,1275 4505,1150 4560,1095 4560,960 4570,950 P1.16
SDOUT: P1.18 U1.9 | length 1023.6
  Top Layer w30: v1(4255,1310) 4270,1295 4620,1295 v1(4630,1305)
  Bottom Layer w15: v1(4255,1310) 4255,1354.64 4316.02,1415.67 U1.9
  Bottom Layer w20: v1(4630,1305) 4635,1300 4635,1160 4685,1110 4685,925 4665,905 P1.18
VA: C1.1 C2.1 C20.1 C33.1 C34.1 C38.1 C39.1 D1.2 D2.2 D5.2 D6.2 R1.1 R10.1 R20.1 U1.19 U4.8 | length 6418.4
  Top Layer w30: C34.1 4430,3480 4490,3420 4735,3420 v2(4795,3360) ; D6.2 D5.2 4449.76,2260 D2.2 D1.2 4409.76,2000.24 4450,1960 4860,1960 C20.1
  Bottom Layer w15: U1.19 4392.8,1847.8 4405,1860
  Bottom Layer w20: 4405,1860 4405,1960 4410,1965 C2.1 C2.1@4410,2025
  Bottom Layer w30: R10.1 4105,3360 4430,3360 ; C1.1 4389.76,2240 D2.2 4449.76,2260 D5.2 D6.2 4565,2434.76 4565,3065 4430,3200 C34.1 ; D2.2@4409.76,2230.24 D1.2 4409.76,2020.24 C2.1 ; R1.1@4745,1015 R1.1 4845,1110 4905,1110 4950,1065 5010,1065 5075,1130 5075,1495 C33.1 5160,1510 5195,1545 5195,1645 5145,1695 5050,1695 4970,1775 C20.1 ; v2(4795,3360) 5105,3360 R20.1@5157.5,3307.5 ; C20.1@4990,1850 C20.1 ; C39.1 C39.1@5230,1910 ; U4.8 5445,1875 5410,1910 C38.1 C39.1@5230,1910 ; C20.1 5030,1910 C39.1@5230,1910
VL: C6.1 C9.1 C35.1 D3.2 L4.1 R2.2 R3.2 R4.2 R5.2 R6.2 R15.2 R16.2 R17.2 U1.8 | length 3389.5
  Top Layer w30: v1(4255,1210) 4275,1230 4785,1230 v1(4795,1240)
  Bottom Layer w15: 4320,1375 4341.61,1396.61 U1.8
  Bottom Layer w20: C9.1@4170,1225 4180,1225 4270,1225 4320,1275 4320,1375
  Bottom Layer w30: C35.1@3570,1090 3570,1145 3645,1220 3665,1220 ; R2.2 3585,2155 3585,1960 ; R16.2 3690,1900 3660,1930 R3.2 3615,1930 3585,1960 ; R5.2 C9.1@4170,1215 ; R5.2@3960,1220 R6.2 3665,1220 ; R4.2 4805.2,1359.8 ; v1(4795,1240) 4810,1255 4810,1355 ; 4805.2,1355 4810,1355 ; D3.2@4980,1430 4885,1430 L4.1 4810,1355 ; 3585,1960 3585,1300 3665,1220
VQ: C13.1 C14.2 U1.22 | length 561.5
  Bottom Layer w15: U1.22 4469.57,1774.57 C14.2@4555,1860
  Bottom Layer w20: C14.2@4555,1860 4555,1880 4605,1930 4730,1930 4840,2040 C13.1
VRL_1: R10.2 R18.1 U9.5 | length 360.7
  Bottom Layer w30: U9.5 3895,3050 R18.1 4035,3200 R10.2
VRL_2: C15.1 C16.1 R8.1 R18.2 U9.3 | length 610.7
  Top Layer w30: U9.3 C15.1
  Bottom Layer w30: R18.2 4075,2920 U9.3 ; C15.1 4385,2800 C16.1 R8.1
VRR_1: R20.2 R22.1 U10.5 | length 293.8
  Bottom Layer w30: U10.5 5070,3100 R22.1 5100,3170 5150,3220 R20.2
VRR_2: C17.1 C28.1 R21.1 R22.2 U10.3 | length 706.1
  Top Layer w30: U10.3 5480,2920 C28.1@5490,2930
  Bottom Layer w30: R22.2 5205,3085 5205,2950 5235,2920 U10.3 ; C28.1@5490,2930 5490,2820 R21.1 C17.1
pads on no net: J18.0 P1.22 P1.25 U4.5

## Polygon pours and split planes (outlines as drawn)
GND on Top Layer "GND" (solid, remove dead copper, pour order 1002): 3505,4378.4 3893.09,4378.4 3882.46,4388.45 3882.46,4694.97 5328.49,4694.97 5333.81,4700 5339.12,4694.97 5339.12,4418.6 5690,4418.6 5690,1080.58 5477.03,1080.58 5357.59,967.68 5357.59,690 3756.88,693.65 3756.88,1050.43 3505,1050.43
GND on Bottom Layer "GND" (solid, remove dead copper, pour order 1000): 3504.94,4391.32 3767.33,4391.49 3882.37,4501.99 3882.41,4697.7 5328.48,4697.7 5333.8,4702.72 5339.11,4697.7 5339.11,4421.46 5690,4421.46 5690,1087.24 5487.99,1087.24 5362.12,967.63 5362.12,699.71 3761.94,697.72 3761.94,1012.83 3504.94,1012.83

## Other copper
Bottom Layer:
  rectangle net GND: 5345,1500 5400,1845
  text "TGM" at 3965,4640 h45
  text "WaS" at 3960,4575 h45
  text "Here" at 3965,4505 h45
  text "28 Aug 15" at 3580,4400 h45 r90
  text "ADC CS5381KZZ" at 5665,3860 h45 r90

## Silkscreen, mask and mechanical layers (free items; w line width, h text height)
Top Overlay:
  lines w20: 3505,695 3505,4710 5695,4710 5695,695 3505,695
  text "K" at 3705,2060 h60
